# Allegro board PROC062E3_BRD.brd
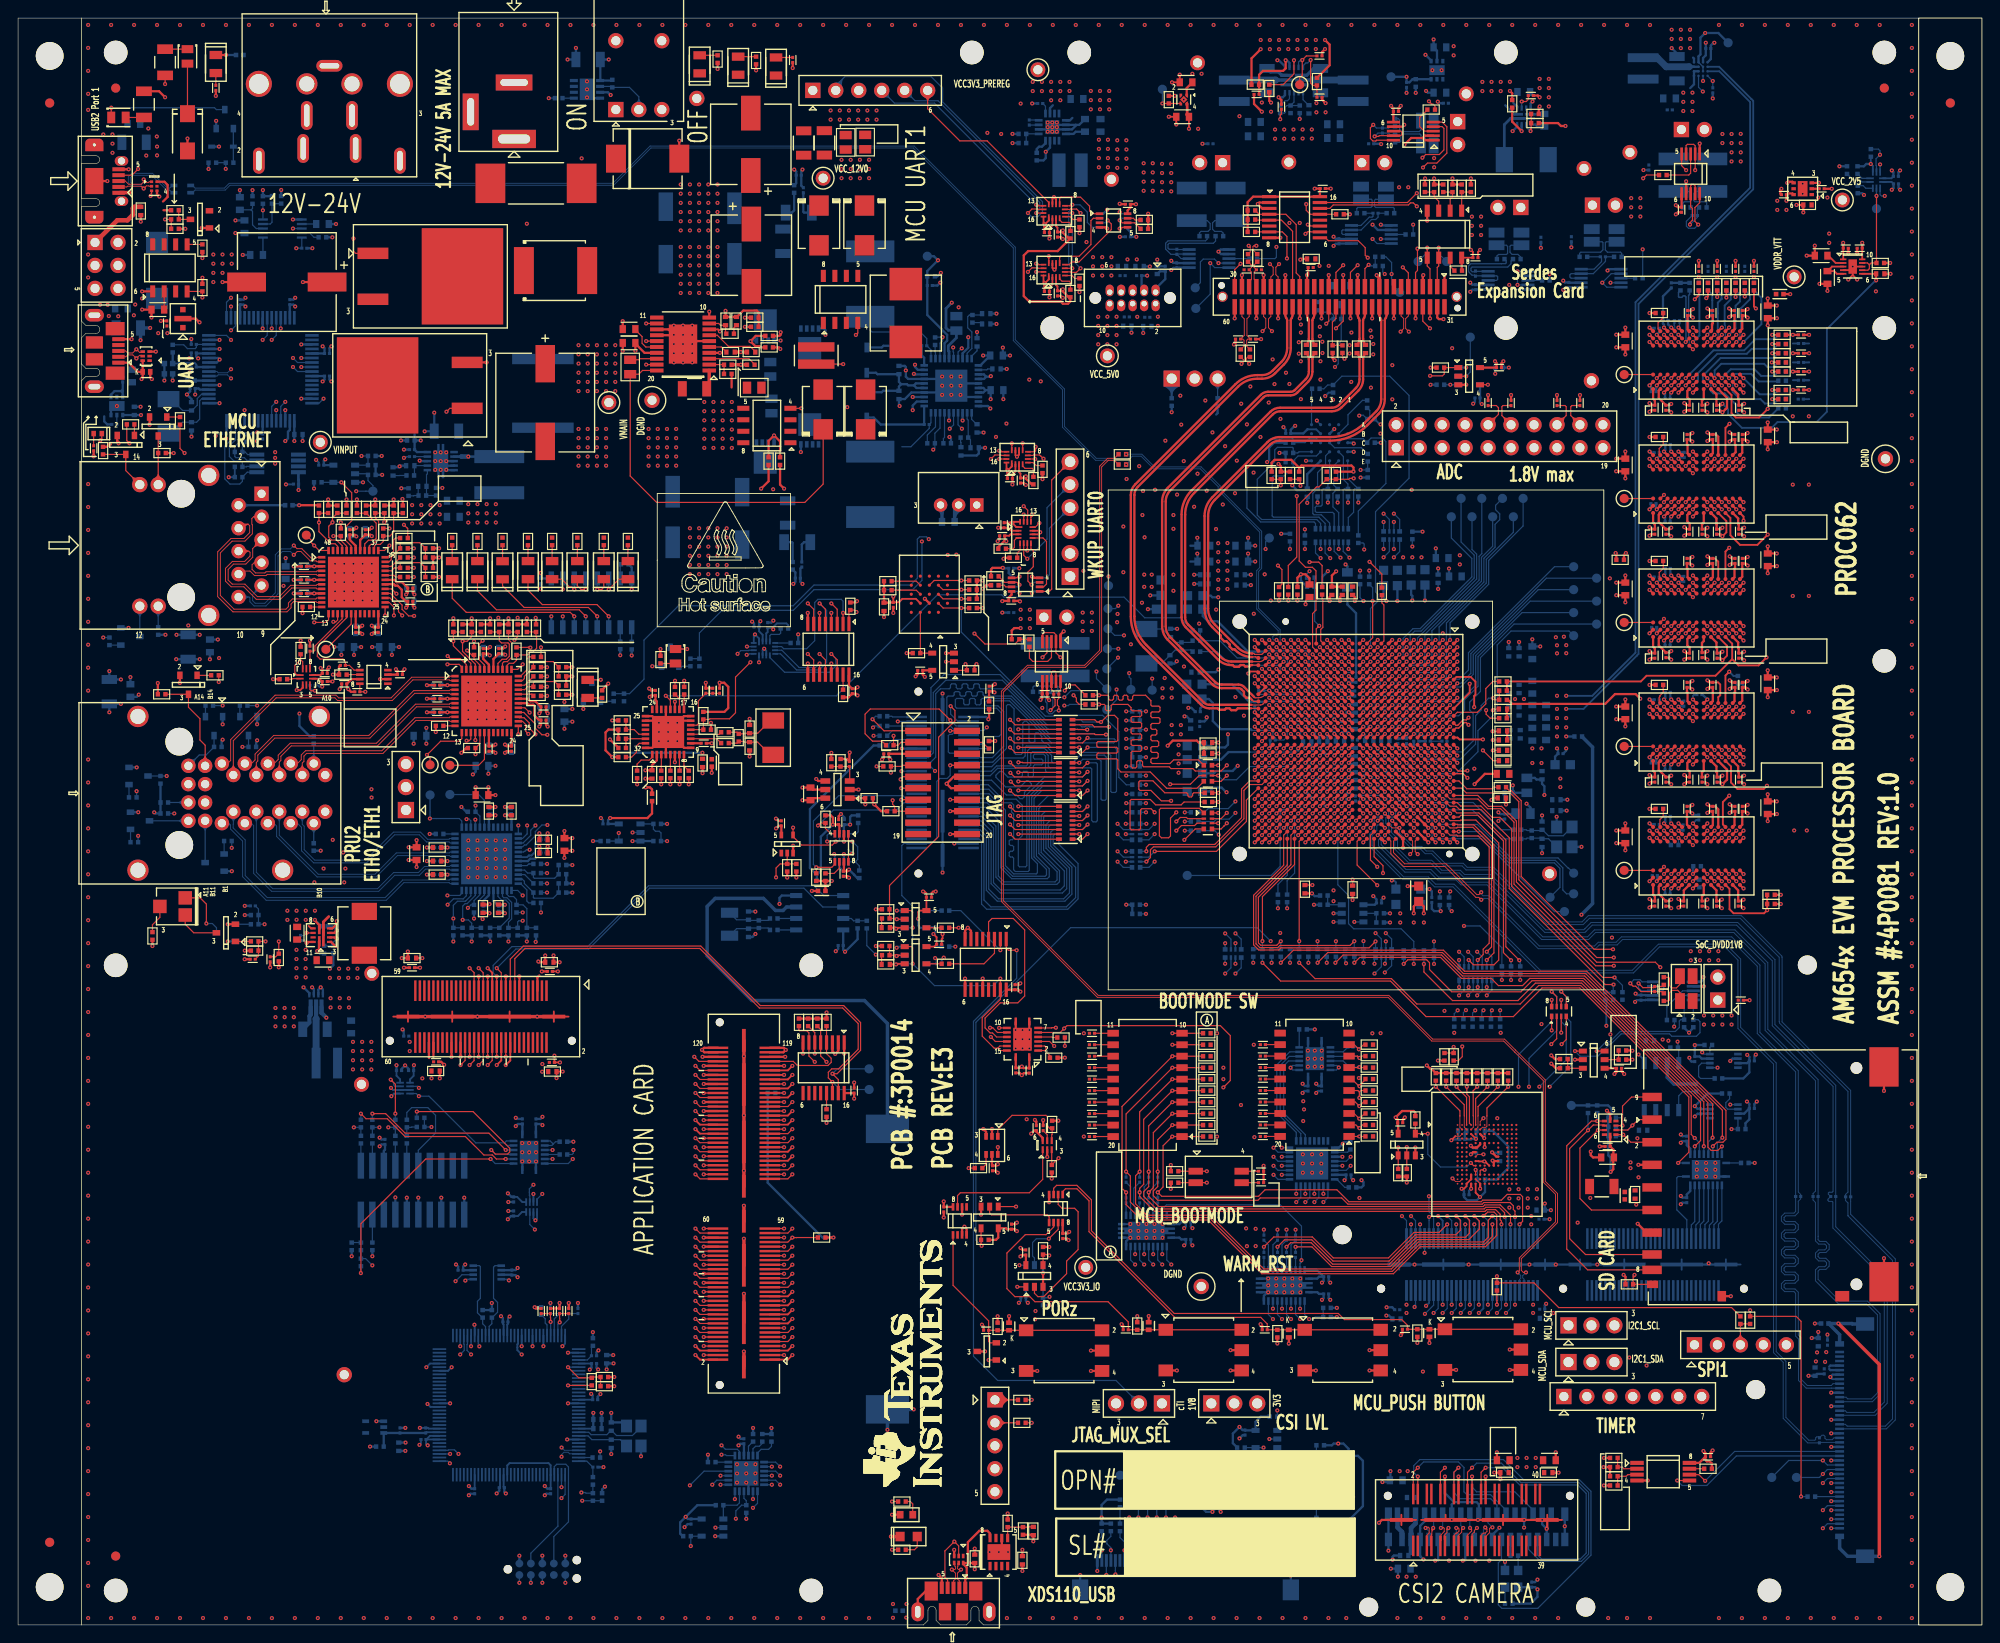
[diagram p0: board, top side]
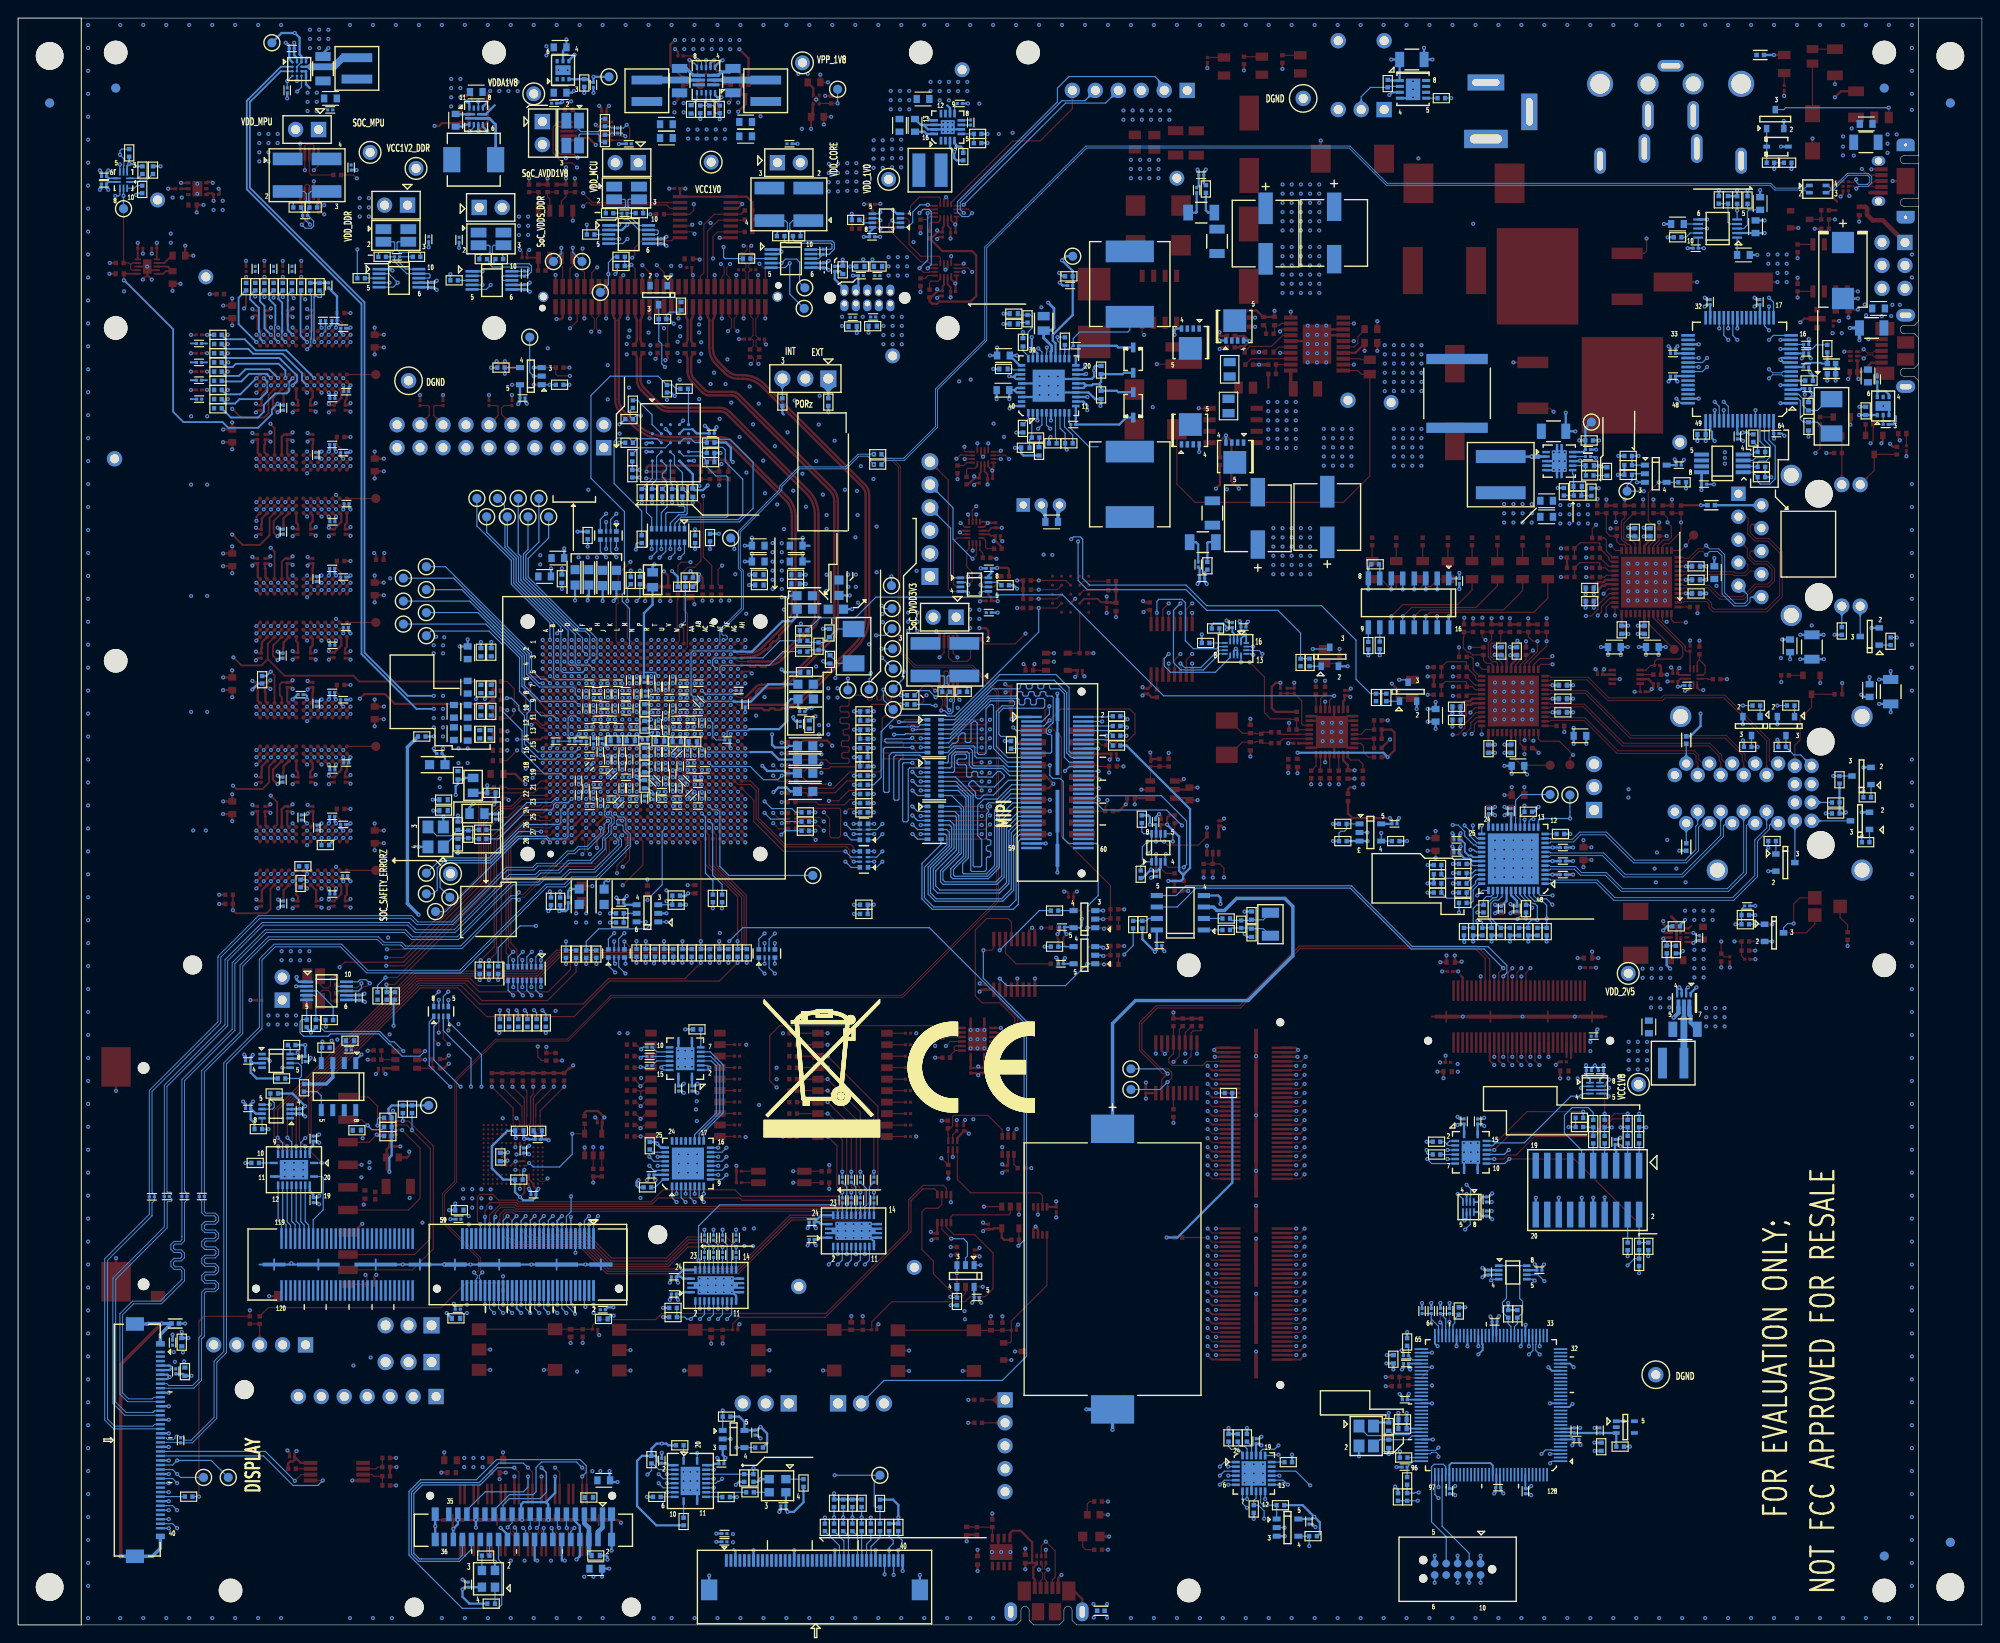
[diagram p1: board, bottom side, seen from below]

Outline 217.17 x 177.8 mm; copper layers: TOP, L02_GND1, L03_SIG1, L04_GND2, L05_SIG2, L06_PWR1, L07_PWR2, L08_PWR3, L09_GND3, L10_SIG3, L11_GND4, L12_SIG4, L13_GND5, BOTTOM. Coordinates in mm from the lower left corner of the outline.
Outline path: rectangle 210.19,0 217.17,177.8 ; 6.99,0 0,0 0,177.8 6.99,177.8 ; 6.99,0 6.99,137.65 7.48,138.15 8.58,138.15 arc(9.03,138.6) 8.58,139.05 7.48,139.05 6.99,139.55 6.99,142.39 7.48,142.89 8.58,142.89 arc(9.03,143.34) 8.58,143.79 7.48,143.79 6.99,144.29 6.99,156.97 8.6,156.97 arc(9.03,157.39) 8.6,157.82 6.99,157.82 6.99,161.72 8.6,161.72 arc(9.03,162.14) 8.6,162.57 6.99,162.57 6.99,177.8 ; 6.99,0 6.99,177.8 ; 6.99,0 100.12,0 100.12,0 100.62,0.5 100.62,1.6 arc(101.07,2.05) 101.52,1.6 101.52,0.5 102.02,0 104.87,0 104.87,0 105.37,0.5 105.37,1.6 arc(105.82,2.05) 106.27,1.6 106.27,0.5 106.77,0 210.19,0 210.19,177.8 6.99,177.8

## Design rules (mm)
net group CSI_REF_CLK_1V8: nets CSI_REF_CLK_1V8 N18001866
net group CSI_REF_CLK_3V3: nets CSI_REF_CLK_3V3 N18289892
net group DDR_DQ0: nets DDR_DQS0_N DDR_DQS0_P
net group DDR_DQS: nets DDR_DQS_N DDR_DQS_P
net group DDR_DQS1: nets DDR_DQS1_N DDR_DQS1_P
net group DDR_DQS2: nets DDR_DQS2_N DDR_DQS2_P
net group DDR_DQS3: nets DDR_DQS3_N DDR_DQS3_P
net group FT4232_USB_D: nets FT4232_USB_DM FT4232_USB_DP
net group MCU_ETH_D0: nets MCU_ETH_D0M MCU_ETH_D0P
net group MCU_ETH_D1: nets MCU_ETH_D1M MCU_ETH_D1P
net group MCU_ETH_D2: nets MCU_ETH_D2M MCU_ETH_D2P
net group MCU_ETH_D3: nets MCU_ETH_D3M MCU_ETH_D3P
net group MCU_RGMII1_CLKIN: nets MCU_RGMII1_CLKIN N16248965
net group MCU_SPI0_CLK/BOOTMODE6: nets MCU_SPI0_CLK MCU_SPI0_CLK/BOOTMODE6
net group MIPI_TRC_DAT00: nets PRG2_RGMII1_RD2 PRG2_RGMII1_RD2_R
net group MIPI_TRC_DAT01: nets PRG2_RGMII1_RD3 PRG2_RGMII1_RD3_R
net group MIPI_TRC_DAT02: nets PRG2_RGMII1_RX_CTL PRG2_RGMII1_RX_CTL_R
net group MIPI_TRC_DAT03: nets PRG2_RGMII1_RXC PRG2_RGMII1_RXC_R
net group MIPI_TRC_DAT05: nets MIPI_TRC_DAT05 PRG2_MDIO
net group MIPI_TRC_DAT11: nets PRG2_RGMII2_RD0 PRG2_RGMII2_RD0_R
net group MIPI_TRC_DAT12: nets PRG2_RGMII2_RD1 PRG2_RGMII2_RD1_R
net group MIPI_TRC_DAT13: nets PRG2_RGMII2_RD2 PRG2_RGMII2_RD2_R
net group MIPI_TRC_DAT14: nets PRG2_RGMII2_RD3 PRG2_RGMII2_RD3_R
net group MIPI_TRC_DAT15: nets PRG2_RGMII2_RX_CTL PRG2_RGMII2_RX_CTL_R
net group MIPI_TRC_DAT16: nets PRG2_RGMII2_RXC PRG2_RGMII2_RXC_R
net group MIPI_TRC_DAT18: nets MIPI_TRC_DAT18 PRG2_MDC
net group MMC0_CLK: nets MMC0_CLK SOC_MMC0_CLK
net group MMC0_DS: nets MMC0_DS SOC_MMC0_DS
net group OSPI_DQS: nets N15352717 OSPI_DQS
net group OSPI_LBCLKO_GPIO: nets OSPI_LBCLKO_GPIO PCIE_GPIO_RESET_IN
net group PCIE1_SGMII1_TXN1: nets PCIE1_SGMII1_TXN1 PCIE1_SGMII1_TXN1_C
net group PCIE1_SGMII1_TXP1: nets PCIE1_SGMII1_TXP1 PCIE1_SGMII1_TXP1_C
net group PRG0_RGMII1_ETH1_CLK: nets N16248943 PRG0_RGMII1_ETH1_CLK
net group PRG0_RGMII2_ETH2_CLK: nets N16248921 PRG0_RGMII2_ETH2_CLK
net group PRG1_RGMII1_ETH1_CLK: nets N16248899 PRG1_RGMII1_ETH1_CLK
net group PRG1_RGMII2_ETH2_CLK: nets N16248877 PRG1_RGMII2_ETH2_CLK
net group PRG2_ETH1_D0: nets PRG2_ETH1_D0M PRG2_ETH1_D0P
net group PRG2_ETH1_D1: nets PRG2_ETH1_D1M PRG2_ETH1_D1P
net group PRG2_ETH1_D2: nets PRG2_ETH1_D2M PRG2_ETH1_D2P
net group PRG2_ETH1_D3: nets PRG2_ETH1_D3M PRG2_ETH1_D3P
net group PRG2_ETH2_D0: nets PRG2_ETH2_D0M PRG2_ETH2_D0P
net group PRG2_ETH2_D1: nets PRG2_ETH2_D1M PRG2_ETH2_D1P
net group PRG2_ETH2_D2: nets PRG2_ETH2_D2M PRG2_ETH2_D2P
net group PRG2_ETH2_D3: nets PRG2_ETH2_D3M PRG2_ETH2_D3P
net group PRG2_RGMII1_ETH1_CLK: nets N16248855 PRG2_RGMII1_ETH1_CLK
net group PRG2_RGMII2_ETH2_CLK: nets N16248833 PRG2_RGMII2_ETH2_CLK
net group PWR: nets SOC_DDR_VREFCA SOC_DVDD1V8
net group REFCLK0N: nets REFCLK0N REFCLK0N_R
net group REFCLK0P: nets REFCLK0P REFCLK0P_R
net group REFCLK1N: nets REFCLK1N REFCLK1N_R
net group REFCLK1P: nets REFCLK1P REFCLK1P_R
net group SOC_MMC0_CMD: nets MMC0_CMD SOC_MMC0_CMD
net group SOC_MMC0_DAT0: nets MMC0_DAT0 SOC_MMC0_DAT0
net group SOC_MMC0_DAT1: nets MMC0_DAT1 SOC_MMC0_DAT1
net group SOC_MMC0_DAT2: nets MMC0_DAT2 SOC_MMC0_DAT2
net group SOC_MMC0_DAT3: nets MMC0_DAT3 SOC_MMC0_DAT3
net group SOC_MMC0_DAT4: nets MMC0_DAT4 SOC_MMC0_DAT4
net group SOC_MMC0_DAT5: nets MMC0_DAT5 SOC_MMC0_DAT5
net group SOC_MMC0_DAT6: nets MMC0_DAT6 SOC_MMC0_DAT6
net group SOC_MMC0_DAT7: nets MMC0_DAT7 SOC_MMC0_DAT7
net group SOC_SERDES_REFCLK0_: nets SOC_SERDES_REFCLK0_N SOC_SERDES_REFCLK0_P
net group SOC_SERDES_REFCLK1_: nets SOC_SERDES_REFCLK1_N SOC_SERDES_REFCLK1_P
net group SOC_SPI0_CLK: nets SOC_SPI0_CLK SOC_SPI0_CLK_R
net group SOC_SPI1_CLK: nets SOC_SPI1_CLK SOC_SPI1_CLK_R
net group SOC_TDO: nets N18125082 SOC_TDO
net group USB0_D: nets USB0_DM USB0_DP
net group USB1_AB_D: nets USB1_AB_DM USB1_AB_DP
net group USB1_CM_D: nets USB1_CM_DM USB1_CM_DP
net group USB1_D: nets USB1_DM USB1_DP
net group USB1_HDMI_GPMC_D: nets USB1_HDMI_GPMC_DM USB1_HDMI_GPMC_DP
net group WKUP_OSC0_XIN: nets N16248811 WKUP_OSC0_XIN
net group XDS_USB_D: nets XDS_USB_DM XDS_USB_DP
net group DDR_ADDRESS_BUS: nets DDR_A0 DDR_A1 DDR_A2 DDR_A3 DDR_A4 DDR_A5 DDR_A6 DDR_A7 DDR_A8 DDR_A9 DDR_A10 DDR_A11 DDR_A12 DDR_A13
net group DDR_DATA_BUS_PH: nets DDR_DM0 DDR_DM1 DDR_DM2 DDR_DM3 DDR_DM4 DDR_DQ0 DDR_DQ1 DDR_DQ2 DDR_DQ3 DDR_DQ4 DDR_DQ5 DDR_DQ6 DDR_DQ7 DDR_DQ8 DDR_DQ9 DDR_DQ10 DDR_DQ11 DDR_DQ12 DDR_DQ13 DDR_DQ14 DDR_DQ15 DDR_DQ16 DDR_DQ17 DDR_DQ18 DDR_DQ19 DDR_DQ20 DDR_DQ21 DDR_DQ22 DDR_DQ23 DDR_DQ24 DDR_DQ25 DDR_DQ26 DDR_DQ27 DDR_DQ28 DDR_DQ29 DDR_DQ30 DDR_DQ31 DDR_DQ36 DDR_DQ37 DDR_DQ38 DDR_DQ39 DDR_DQ40 DDR_DQ41 DDR_DQ42
net group MCU_RGMII1_RD0: nets MCU_RGMII1_RD0
net group MCU_RGMII1_RD1: nets MCU_RGMII1_RD1
net group MCU_RGMII1_RD2: nets MCU_RGMII1_RD2
net group MCU_RGMII1_RD3: nets MCU_RGMII1_RD3
net group MCU_RGMII1_RX_CTL: nets MCU_RGMII1_RX_CTL
net group MCU_RGMII1_RXC: nets MCU_RGMII1_RXC
net group MCU_RGMII1_TD0: nets MCU_RGMII1_TD0
net group MCU_RGMII1_TD1: nets MCU_RGMII1_TD1
net group MCU_RGMII1_TD2: nets MCU_RGMII1_TD2
net group MCU_RGMII1_TD3: nets MCU_RGMII1_TD3
net group MCU_RGMII1_TX_CTL: nets MCU_RGMII1_TX_CTL
net group MCU_RGMII1_TXC: nets MCU_RGMII1_TXC
net group MIPI_TRC_CLK: nets PRG2_PRU0_GP0 PRG2_RGMII1_RD0 PRG2_RGMII1_RD0_R
net group MIPI_TRC_CTL: nets PRG2_PRU0_GP1 PRG2_RGMII1_RD1 PRG2_RGMII1_RD1_R
net group MIPI_TRC_DAT04: nets PRG2_RGMII1_TX_CTL
net group MIPI_TRC_DAT06: nets PRG2_RGMII1_TD0
net group MIPI_TRC_DAT07: nets PRG2_RGMII1_TD1
net group MIPI_TRC_DAT08: nets PRG2_RGMII1_TD2
net group MIPI_TRC_DAT09: nets PRG2_RGMII1_TD3
net group MIPI_TRC_DAT10: nets PRG2_RGMII1_TXC
net group MIPI_TRC_DAT17: nets PRG2_RGMII2_TX_CTL
net group MIPI_TRC_DAT19: nets PRG2_RGMII2_TD0
net group MIPI_TRC_DAT20: nets PRG2_RGMII2_TD1
net group MIPI_TRC_DAT21: nets PRG2_RGMII2_TD2
net group MIPI_TRC_DAT22: nets PRG2_RGMII2_TD3
net group MIPI_TRC_DAT23: nets PRG2_RGMII2_TXC
net group OSPI_CLK: nets N20584902 OSPI_CLK SOC_OSPI_CLK
net group SOC_TCK: nets N16937764 N16938293 SOC_TCK
net group USB0_PCIE0_SGMII0_TXN0: nets USB0_PCIE0_SGMII0_TXN0_C

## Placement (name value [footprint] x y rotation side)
ACC*  -  [unnamed#3]  147.96 98.17 270 top
B1  796136-1  [BATTH2_796136_1080X750_SMD_6-9]  96.14 39.37 270 bottom
C1  1uF  [CAP0603_1]  128.78 166.88 180 top
C2  0.01uF  [CAP0201_0-5]  136.96 169.35 180 top
C3  0.01uF  [CAP0201_0-5]  167.28 169.23 0 top
C4  0.1uF  [CAP0201_0-5]  139.7 167.98 270 top
C5  1uF  [CAP0603_1]  129.16 170.69 180 top
C6  0.1uF  [CAP0201_0-5]  152.37 167.47 0 top
C7  0.47uF  [CAP0805_1]  93.68 164.08 90 top
C8  0.47uF  [CAP0805_1]  91.52 164.05 90 top
C9  47uF  [CAP1206_2]  89.17 163.99 90 top
C10  47uF  [CAP1206_2]  86.88 163.97 90 top
C11  1000pF  [CAP1206]  12.83 164.06 180 bottom
C12  150uF_25V  [CAPAE_CASE8383_11]  81.03 163.83 90 top
C13  0.1uF  [CAP0201_0-5]  144.27 158.94 0 top
C14  0.01uF  [CAP0201_0-5]  199.44 158.91 0 top
C15  0.1uF  [CAP0201_0-5]  195.28 158.26 180 top
C16  0.1uF  [CAP0201_0-5]  122.73 157.2 180 top
C17  2.2uF  [CAP0402_0-75]  197.88 157.12 180 top
C18  0.1uF  [CAP0201_0-5]  183.96 156.59 270 top
C19  4.7uF  [CAP0402_0-75]  13.57 156.45 270 top
C20  0.1uF  [CAP0201_0-5]  113.78 154.06 180 top
C21  0.1uF  [CAP0201_0-5]  114.94 153.85 270 top
C22  0.1uF  [CAP0201_0-5]  202.11 152.34 0 top
C23  0.1uF  [CAP0201_0-5]  203.65 152.34 180 top
C24  150uF_25V  [CAPAE_CASE8383_11]  81.09 151.56 270 top
C25  10uF  [CAP0603_1]  199.39 151.51 180 top
C26  1uF  [CAP0402_0-75]  143 151.15 180 top
C29  0.1uF  [CAP0201_0-5]  142.94 150.2 180 top
C30  0.1uF  [CAP0201_0-5]  185.86 150.05 90 top
C31  0.1uF  [CAP0201_0-5]  190.94 150.05 90 bottom
C32  0.1uF  [CAP0201_0-5]  187.9 150.05 90 top
C33  0.1uF  [CAP0201_0-5]  188.91 150.05 90 bottom
C34  0.1uF  [CAP0201_0-5]  189.93 150.05 90 top
C35  0.1uF  [CAP0201_0-5]  186.88 150.05 90 bottom
C36  0.1uF  [CAP0201_0-5]  191.96 150.05 90 top
C37  0.22uF  [CAP0402_0-75]  205.93 149.5 0 top
C38  10uF  [CAP0603_1]  200.09 149.1 90 top
C39  22uF_100V  [CAPAE_GCASE]  29.72 148.59 180 top
C40  0.1uF  [CAP0201_0-5]  113.78 147.55 180 top
C41  0.1uF  [CAP0201_0-5]  114.94 147.34 270 top
C42  10uF  [CAP0603_1]  15.45 145.54 180 top
C43  22uF_6.3V  [CAP0603]  193.48 145.29 270 top
C44  0.01uF  [CAP0201_0-5]  184.62 145.16 90 top
C45  0.01uF  [CAP0201_0-5]  187.41 145.16 90 top
C46  0.01uF  [CAP0201_0-5]  189.81 145.16 90 top
C47  0.01uF  [CAP0201_0-5]  190.66 145.16 90 top
C48  100pF  [CAP0402]  78.23 144.27 90 top
C49  820pF  [CAP0402_0-75]  79.44 144.27 90 top
C50  0.1uF  [CAP0201_0-5]  16.45 144.01 90 top
C51  1uF  [CAP0603_1]  67.56 143.38 180 top
C52  0.1uF  [CAP0201_0-5]  197.17 142.75 0 top
C53  22uF_6.3V  [CAP0603]  177.74 142.07 270 top
C56  1uF  [CAP0603_1]  67.56 141.86 180 top
C57  0.1uF  [CAP0201_0-5]  197.17 141.8 0 bottom
C58  0.01uF  [CAP0402_0-75]  142.47 141.18 90 top
C59  0.01uF  [CAP0402_0-75]  143.41 141.18 90 top
C60  0.01uF  [CAP0402_0-75]  148.07 141.18 90 top
C61  0.01uF  [CAP0402_0-75]  149.01 141.18 90 top
C62  220pF  [CAP0402]  78.79 140.84 0 top
C63  0.047uF  [CAP0402_0-75]  81.07 140.84 180 top
C64  0.1uF  [CAP0201_0-5]  197.17 140.71 0 top
C65  0.1uF  [CAP0201_0-5]  197.17 139.7 0 bottom
C66  0.47uF  [CAP0805_1]  67.69 139.19 270 top
C67  0.1uF  [CAP0201_0-5]  197.17 138.68 0 top
C68  2.2uF  [CAP0805_1]  81.41 136.91 0 top
C69  10uF  [CAP1206_2]  74.8 136.78 180 top
C70  0.1uF  [CAP0201_0-5]  197.17 136.65 0 top
C71  0.1uF  [CAP0201_0-5]  197.14 135.64 0 bottom
C72  100uF_63V  [CAPAE_CASE103103_11]  58.29 135.25 270 top
C73  0.1uF  [CAP0201_0-5]  162.56 135.2 90 top
C74  0.1uF  [CAP0201_0-5]  165.1 135.2 90 top
C75  0.1uF  [CAP0201_0-5]  170.18 135.2 90 top
C76  0.1uF  [CAP0201_0-5]  172.72 135.2 90 top
C77  1000pF  [CAP1206]  12.19 143.51 180 bottom
C78  0.01uF  [CAP0201_0-5]  181 134.68 270 top
C79  0.01uF  [CAP0201_0-5]  182.21 134.68 270 top
C80  0.01uF  [CAP0201_0-5]  184.85 134.68 270 top
C81  0.01uF  [CAP0201_0-5]  186.21 134.68 270 top
C82  0.01uF  [CAP0201_0-5]  187.81 134.68 270 top
C83  0.01uF  [CAP0201_0-5]  190.28 134.68 270 top
C85  22uF_6.3V  [CAP0603]  193.48 131.57 90 top
C86  0.01uF  [CAP0201_0-5]  184.55 131.44 90 top
C87  0.01uF  [CAP0201_0-5]  187.41 131.44 90 top
C88  0.01uF  [CAP0201_0-5]  189.86 131.44 90 top
C89  0.01uF  [CAP0201_0-5]  190.66 131.44 90 top
C90  22uF_6.3V  [CAP0603]  177.74 128.35 270 top
C91  0.1uF  [CAP0201_0-5]  109.68 126.84 180 top
C92  0.1uF  [CAP0201_0-5]  110.85 126.63 270 top
C94  0.1uF  [CAP0201_0-5]  109.04 121.68 90 top
C95  0.01uF  [CAP0201_0-5]  181 120.97 270 top
C96  0.01uF  [CAP0201_0-5]  182.21 120.97 270 top
C97  0.01uF  [CAP0201_0-5]  184.85 120.97 270 top
C98  0.01uF  [CAP0201_0-5]  186.21 120.97 270 top
C99  0.01uF  [CAP0201_0-5]  187.83 120.97 270 top
C100  0.01uF  [CAP0201_0-5]  190.27 120.97 270 top
C101  0.1uF  [CAP0201_0-5]  36.68 120.9 90 top
C102  0.1uF  [CAP0201_0-5]  38.39 120.9 90 top
C103  0.1uF  [CAP0201_0-5]  108.83 120.52 180 top
C104  22uF_6.3V  [CAP0603]  193.48 117.86 90 top
C105  0.01uF  [CAP0201_0-5]  184.55 117.73 90 top
C106  0.01uF  [CAP0201_0-5]  187.41 117.73 90 top
C107  0.01uF  [CAP0201_0-5]  189.87 117.73 90 top
C108  0.01uF  [CAP0201_0-5]  190.66 117.73 90 top
C109  0.1uF  [CAP0201_0-5]  31.61 117.14 180 top
C110  0.1uF  [CAP0201_0-5]  31.63 115.64 180 top
C111  0.1uF  [CAP0201_0-5]  43.37 114.74 0 top
C112  22uF_6.3V  [CAP0603]  177.74 114.63 270 top
C113  2.2uF  [CAP0603]  142.81 114.43 270 top
C114  1uF  [CAP0402_0-75]  145.29 114.43 90 top
C115  2.2uF  [CAP0402_0-75]  146.43 114.43 90 top
C116  1uF  [CAP0402_0-75]  147.57 114.43 90 top
C117  0.1uF  [CAP0201_0-5]  31.61 114.14 180 top
C119  0.1uF  [CAP0201_0-5]  109.83 113.31 0 top
C120  0.1uF  [CAP0201_0-5]  43.37 113.28 0 top
C121  0.1uF  [CAP0201_0-5]  96.79 112.87 270 top
C122  4.7uF  [CAP0402_0-75]  95.76 112.65 270 top
C123  0.1uF  [CAP0201_0-5]  37.33 110.11 270 top
C124  0.1uF  [CAP0201_0-5]  39.83 110.11 270 top
C125  0.1uF  [CAP0201_0-5]  51.44 107.75 90 top
C126  0.1uF  [CAP0201_0-5]  53.15 107.75 90 top
C127  0.01uF  [CAP0201_0-5]  182.21 107.31 270 top
C128  0.01uF  [CAP0201_0-5]  186.21 107.31 270 top
C129  0.01uF  [CAP0201_0-5]  181 107.25 270 top
C130  0.01uF  [CAP0201_0-5]  184.85 107.25 270 top
C131  0.01uF  [CAP0201_0-5]  187.88 107.25 270 top
C132  0.01uF  [CAP0201_0-5]  190.27 107.25 270 top
C133  0.1uF  [CAP0201_0-5]  99.76 105.63 180 top
C134  0.1uF  [CAP0201_0-5]  33.91 105.28 0 top
C135  0.1uF  [CAP0201_0-5]  42.23 105.16 0 top
C136  0.1uF  [CAP0201_0-5]  33.91 104.39 0 top
C137  22uF_6.3V  [CAP0603]  193.48 104.14 90 top
C138  0.1uF  [CAP0201_0-5]  36.07 104.14 180 top
C139  0.01uF  [CAP0201_0-5]  184.55 104.01 90 top
C140  0.01uF  [CAP0201_0-5]  187.41 104.01 90 top
C141  0.01uF  [CAP0201_0-5]  189.87 104.01 90 top
C142  0.01uF  [CAP0201_0-5]  190.66 104.01 90 top
C143  0.1uF  [CAP0201_0-5]  46.34 103.98 180 top
C144  0.1uF  [CAP0201_0-5]  107.38 103.59 90 top
C145  0.1uF  [CAP0201_0-5]  76.83 103.37 90 top
C146  0.1uF  [CAP0201_0-5]  92.23 103.32 270 top
C147  0.1uF  [CAP0201_0-5]  70.48 103.12 90 top
C148  0.1uF  [CAP0201_0-5]  113.53 103.03 0 top
C149  0.1uF  [CAP0201_0-5]  46.36 102.48 180 top
C150  0.1uF  [CAP0201_0-5]  58.1 101.59 0 top
C151  1uF  [CAP0402_0-75]  164.21 101.35 0 top
C153  0.1uF  [CAP0201_0-5]  46.34 100.99 180 top
C154  22uF_6.3V  [CAP0603]  177.74 100.92 270 top
C155  0.1uF  [CAP0201_0-5]  58.1 100.13 0 top
C156  18pF  [CAP0402_0-75]  80.9 99.13 270 top
C157  1uF  [CAP0402_0-75]  164.21 98.93 0 top
C158  1uF  [CAP0402_0-75]  164.21 97.92 0 top
C159  1uF  [CAP0402_0-75]  131.6 97.64 180 top
C160  0.1uF  [CAP0201_0-5]  75.82 97.56 0 top
C161  18pF  [CAP0402_0-75]  80.9 97.22 90 top
C162  0.1uF  [CAP0201_0-5]  52.07 96.96 270 top
C163  0.1uF  [CAP0201_0-5]  54.57 96.96 270 top
C164  1uF  [CAP0402_0-75]  164.21 96.77 0 top
C165  1uF  [CAP0402_0-75]  131.6 96.43 180 top
C166  0.1uF  [CAP0201_0-5]  96.01 96.39 180 top
C167  1uF  [CAP0402_0-75]  164.21 95.63 0 top
C168  0.01uF  [CAP0201_0-5]  91.92 95.26 90 top
C169  1uF  [CAP0402_0-75]  75.69 95.38 90 top
C170  2.2uF  [CAP0603]  164.21 94.17 180 top
C171  1uF  [CAP0402_0-75]  70.1 94.11 90 top
C172  0.01uF  [CAP0201_0-5]  181 93.54 270 top
C173  0.01uF  [CAP0201_0-5]  182.21 93.54 270 top
C174  0.01uF  [CAP0201_0-5]  184.85 93.54 270 top
C175  0.01uF  [CAP0201_0-5]  186.21 93.54 270 top
C176  0.01uF  [CAP0201_0-5]  187.88 93.54 270 top
C177  0.01uF  [CAP0201_0-5]  190.27 93.54 270 top
C178  10uF  [CAP0603_1]  51.3 91.82 180 top
C179  0.1uF  [CAP0603_1]  87.63 91.96 270 top
C180  2.2uF  [CAP0402_0-75]  164.08 91.5 0 top
C181  22uF_6.3V  [CAP0603]  193.48 90.42 90 top
C182  0.01uF  [CAP0201_0-5]  184.55 90.3 90 top
C183  0.01uF  [CAP0201_0-5]  187.41 90.3 90 top
C184  0.01uF  [CAP0201_0-5]  189.87 90.3 90 top
C185  0.01uF  [CAP0201_0-5]  190.66 90.3 90 top
C186  1uF  [CAP0402_0-75]  52.07 90.05 90 top
C187  1uF  [CAP0402_0-75]  54.57 90.05 90 top
C188  0.1uF  [CAP0201_0-5]  90.74 88.84 90 top
C189  0.1uF  [CAP0201_0-5]  84.4 88.7 90 top
C190  22uF_6.3V  [CAP0603]  177.74 87.2 270 top
C192  1uF  [CAP0402_0-75]  58.1 86.88 0 top
C193  10uF  [CAP0603_1]  60.41 86.36 90 top
C194  1uF  [CAP0402_0-75]  46.34 86.02 180 top
C195  1uF  [CAP0402_0-75]  58.1 85.41 0 top
C196  10uF  [CAP0603_1]  44.07 85.34 270 top
C197  1uF  [CAP0402_0-75]  46.34 84.52 180 top
C198  0.1uF  [CAP0201_0-5]  91.25 83.12 270 top
C199  1uF  [CAP0402_0-75]  46.34 83.02 180 top
C200  2.2uF  [CAP0402_0-75]  142.3 81.41 270 top
C201  1uF  [CAP0402_0-75]  147.57 81.34 270 top
C202  0.01uF  [CAP0201_0-5]  181 79.82 270 top
C203  0.01uF  [CAP0201_0-5]  182.21 79.82 270 top
C204  0.01uF  [CAP0201_0-5]  184.2 79.82 270 top
C205  0.01uF  [CAP0201_0-5]  186.21 79.82 270 top
C206  0.01uF  [CAP0201_0-5]  187.81 79.82 270 top
C207  0.01uF  [CAP0201_0-5]  190.21 79.82 270 top
C208  1uF  [CAP0402_0-75]  51.41 79.26 270 top
C209  1uF  [CAP0402_0-75]  53.11 79.26 270 top
C210  8.2pF  [CAP0402_0-75]  95.95 77.15 0 top
C211  10uF  [CAP0603_1]  30.86 76.54 270 top
C212  22uF_6.3V  [CAP0603]  33.72 73.56 180 top
C213  1uF  [CAP0402_0-75]  43.56 73.79 180 top
C214  8.2pF  [CAP0402_0-75]  95.95 73.09 0 top
C215  0.1uF  [CAP0201_0-5]  42.93 65.15 180 bottom
C216  0.1uF  [CAP0201_0-5]  43.56 72.72 180 top
C217  0.1uF  [CAP0201_0-5]  110.24 70.57 90 top
C218  0.1uF  [CAP0201_0-5]  180.98 70.36 90 top
C219  0.1uF  [CAP0201_0-5]  190.51 69.13 0 top
C220  0.1uF  [CAP0201_0-5]  186.06 56.84 270 bottom
C221  0.1uF  [CAP0201_0-5]  191.73 57.15 0 bottom
C222  0.1uF  [CAP0201_0-5]  58.8 72.31 0 top
C223  0.1uF  [CAP0201_0-5]  59.03 62.24 0 top
C224  0.01uF  [CAP0201_0-5]  177.04 61.6 180 top
C225  0.1uF  [CAP0201_0-5]  110.32 61.36 270 top
C226  0.1uF  [CAP0201_0-5]  111.82 61.34 270 top
C227  1uF  [CAP0402_0-75]  58.75 73.33 0 top
C228  1uF  [CAP0402_0-75]  59.09 61.23 0 top
C229  0.1uF  [CAP0201_0-5]  92.46 59.13 90 top
C230  0.1uF  [CAP0201_0-5]  152.84 55.56 0 top
C231  0.1uF  [CAP0201_0-5]  112.6 54.98 90 top
C232  0.1uF  [CAP0201_0-5]  113.36 54.98 90 top
C233  0.1uF  [CAP0201_0-5]  175.78 52.95 180 top
C234  0.1uF  [CAP0201_0-5]  107.75 50.54 270 top
C235  2.2uF  [CAP0402_0-75]  178.82 47.62 270 top
C236  0.1uF  [CAP0201_0-5]  102.36 45.97 270 top
C237  0.1uF  [CAP0201_0-5]  109.86 44.07 90 top
C238  0.1uF  [CAP0201_0-5]  115.52 43.04 270 top
C239  0.1uF  [CAP0201_0-5]  111.45 41.21 90 top
C240  0.1uF  [CAP0201_0-5]  153.37 32.72 180 top
C241  0.1uF  [CAP0201_0-5]  137.86 32.65 180 top
C242  0.1uF  [CAP0201_0-5]  122.49 32.65 180 top
C243  0.1uF  [CAP0201_0-5]  107.05 32.6 180 top
C244  0.01uF  [CAP0201_0-5]  186.88 18.61 0 top
C245  10uF  [CAP0603_1]  164.24 18.22 0 top
C246  10uF  [CAP0603_1]  169.34 18.22 180 top
C247  1uF  [CAP0402_0-75]  164.38 16.85 0 top
C248  1uF  [CAP0402_0-75]  169.22 16.85 180 top
C249  15pF  [CAP0402_0-75]  112.27 10.39 90 top
C250  2.2uF  [CAP0402_0-75]  105.79 7.31 90 top
C251  1uF  [CAP0402_0-75]  111.06 7.15 90 top
C252  0.1uF  [CAP0201_0-5]  186.91 174.43 180 bottom
C253  1uF  [CAP0603_1]  157.23 174.56 180 bottom
C254  10uF  [CAP1206_2]  63.04 173.22 180 bottom
C255  10uF  [CAP1206_2]  183.45 172.2 270 bottom
C256  22uF  [CAP1206_2]  144.02 170.88 270 bottom
C257  22uF  [CAP1206_2]  138.11 170.88 270 bottom
C258  0.01uF  [CAP0201_0-5]  153.54 170.41 270 bottom
C259  1uF  [CAP0603_1]  157.23 169.55 180 bottom
C260  10uF  [CAP0603_1]  166.5 169.62 0 bottom
C261  22uF_6.3V  [CAP0603]  182.63 168.91 0 bottom
C262  22uF_6.3V  [CAP0603]  117.1 168.85 0 bottom
C263  0.1uF  [CAP0201_0-5]  157.89 168.38 180 bottom
C264  0.01uF  [CAP0201_0-5]  113.03 168.35 180 bottom
C265  0.01uF  [CAP0402_0-75]  142.75 167.7 270 bottom
C266  0.1uF  [CAP0201_0-5]  182.65 167.64 0 bottom
C267  22uF_6.3V  [CAP0603]  168.78 166.5 90 bottom
C268  47uF  [CAP0603_1]  136.72 166.31 0 bottom
C269  0.01uF  [CAP0201_0-5]  111.82 166.24 270 bottom
C270  47uF  [CAP0603_1]  145.48 166.05 180 bottom
C271  22uF_6.3V  [CAP0603]  119.7 165.93 90 bottom
C272  22uF_6.3V  [CAP0603]  117.98 165.93 90 bottom
C273  0.1uF  [CAP0201_0-5]  150.88 165.35 270 bottom
C274  47uF  [CAP0603_1]  136.72 164.72 0 bottom
C275  47uF  [CAP0603_1]  145.48 164.53 180 bottom
C276  0.1uF  [CAP0201_0-5]  149.63 163.89 0 bottom
C277  0.1uF  [CAP0201_0-5]  131.86 163.89 180 bottom
C278  0.1uF  [CAP0201_0-5]  180.34 161.26 270 bottom
C279  0.1uF  [CAP0201_0-5]  185.42 155.96 0 bottom
C280  0.1uF  [CAP0201_0-5]  150.11 156.21 0 bottom
C281  0.1uF  [CAP0603_1]  33.67 155.01 0 bottom
C282  0.1uF  [CAP0603_1]  25.03 154.71 90 bottom
C283  470uF_10V  [CAPAE_D8CASE_8]  71.63 154.03 270 bottom
C284  270uF_10V  [CAP_87510524_270X270_SMD_7-7]  79.22 153.95 270 bottom
C285  0.1uF  [CAP0201_0-5]  122.73 153.59 180 bottom
C286  0.1uF  [CAP0201_0-5]  128.14 151.94 270 bottom
C287  0.1uF  [CAP0201_0-5]  171.77 153.33 270 bottom
C288  0.1uF  [CAP0201_0-5]  168.4 153.26 270 bottom
C289  0.1uF  [CAP0201_0-5]  146.07 153.1 90 bottom
C290  47uF  [CAP1206_2]  84.58 153.1 270 bottom
C291  0.01uF  [CAP0201_0-5]  31.65 152.34 0 bottom
C292  0.1uF  [CAP0201_0-5]  175.26 151.38 0 bottom
C293  0.1uF  [CAP0201_0-5]  161.16 149.52 270 bottom
C294  0.1uF  [CAP0201_0-5]  128.12 150.44 90 bottom
C295  1uF  [CAP0402_0-75]  124.02 150.31 180 bottom
C296  1uF  [CAP0402_0-75]  122.07 150.31 0 bottom
C297  0.1uF  [CAP0201_0-5]  126.86 150.06 90 bottom
C298  1uF  [CAP0402_0-75]  125.98 149.94 90 bottom
C299  150uF_10V  [CAPT7343D_3-25]  15.37 149.87 270 bottom
C300  0.1uF  [CAP0201_0-5]  123.97 149.3 180 bottom
C301  0.1uF  [CAP0201_0-5]  122.15 149.3 0 bottom
C302  0.1uF  [CAP0201_0-5]  171.5 148.27 90 bottom
C303  0.1uF  [CAP0201_0-5]  182.82 148.22 90 bottom
C304  0.1uF  [CAP0201_0-5]  161.18 148.02 90 bottom
C305  0.1uF  [CAP0201_0-5]  30.05 146.37 270 bottom
C306  0.1uF  [CAP0201_0-5]  24.55 146.37 270 bottom
C307  0.01uF  [CAP0402_0-75]  107.06 143.95 0 bottom
C308  100pF  [CAP0402]  107.06 145.1 0 bottom
C309  0.1uF  [CAP0201_0-5]  122.61 144.73 0 bottom
C310  0.1uF  [CAP0201_0-5]  124.87 144.69 180 bottom
C311  0.01uF  [CAP0201_0-5]  183.45 144.34 0 bottom
C312  0.01uF  [CAP0201_0-5]  182.18 144.34 0 bottom
C313  1uF  [CAP0402_0-75]  122.67 143.71 0 bottom
C314  1uF  [CAP0402_0-75]  124.88 143.68 180 bottom
C315  0.01uF  [CAP0201_0-5]  181.22 143.49 180 bottom
C316  0.01uF  [CAP0201_0-5]  100.83 148.21 0 bottom
C317  0.056uF  [CAP0402_0-75]  106.05 141.92 90 bottom
C318  0.47uF  [CAP0603_1]  108.25 136.63 0 bottom
C319  0.1uF  [CAP0201_0-5]  19.43 141.69 0 bottom
C320  0.1uF  [CAP0201_0-5]  100.2 141.54 0 bottom
C321  0.1uF  [CAP0201_0-5]  19.43 140.75 0 bottom
C322  0.1uF  [CAP0201_0-5]  34.16 140.69 180 bottom
C323  0.1uF  [CAP0603_1]  108.2 140.46 0 bottom
C324  0.1uF  [CAP0201_0-5]  19.43 139.19 0 bottom
C325  1uF  [CAP0402_0-75]  108.2 138.97 180 bottom
C326  0.1uF  [CAP0201_0-5]  34.16 138.19 180 bottom
C327  10uF  [CAP0603_1]  12.6 138.2 270 bottom
C328  0.1uF  [CAP0201_0-5]  197.17 137.73 0 bottom
C329  0.1uF  [CAP0201_0-5]  11.57 137.82 270 bottom
C330  4.7uF  [CAP0402_0-75]  97.41 138.85 90 bottom
C331  0.1uF  [CAP0201_0-5]  19.3 136.82 0 bottom
C332  0.01uF  [CAP0201_0-5]  180.88 136.46 180 bottom
C333  22uF  [CAP7563_4]  58.04 136.27 270 bottom
C334  0.1uF  [CAP0201_0-5]  161.38 135.76 180 bottom
C335  0.01uF  [CAP0201_0-5]  182.41 135.7 0 bottom
C336  1uF  [CAP0603_1]  102.87 122.05 180 bottom
C337  18pF  [CAP0402_0-75]  19.18 134.84 90 bottom
C338  0.01uF  [CAP0201_0-5]  187.81 134.68 270 bottom
C339  2.2uF  [CAP0402_0-75]  12.85 134.33 90 bottom
C340  0.47uF  [CAP0805_1-5]  103.76 144.02 90 bottom
C341  10uF  [CAP1206_2]  47.37 132.08 180 bottom
C342  0.01uF  [CAP0201_0-5]  10.64 132.84 180 bottom
C343  0.1uF  [CAP0201_0-5]  100.48 132.83 180 bottom
C344  18pF  [CAP0402_0-75]  19.18 132.62 270 bottom
C345  0.056uF  [CAP0402_0-75]  106.05 132.4 270 bottom
C346  0.1uF  [CAP0201_0-5]  140.46 131.84 180 bottom
C347  3.3uF  [CAP0402]  31.01 131.72 180 bottom
C348  0.1uF  [CAP0201_0-5]  27.05 131.51 90 bottom
C349  0.1uF  [CAP0201_0-5]  22.73 131.83 0 bottom
C350  100pF  [CAP0402]  105.78 130.25 0 bottom
C351  0.01uF  [CAP0201_0-5]  182.44 130.62 0 bottom
C352  0.01uF  [CAP0402_0-75]  104.27 129.86 270 bottom
C353  0.01uF  [CAP0201_0-5]  43.56 130.05 180 bottom
C354  0.01uF  [CAP0201_0-5]  181.22 129.71 180 bottom
C355  0.01uF  [CAP0201_0-5]  184.25 129.47 90 bottom
C356  0.1uF  [CAP0201_0-5]  43.56 129.28 180 bottom
C357  150pF  [CAP0402_0-75]  43.37 128.27 180 bottom
C358  0.1uF  [CAP0201_0-5]  33.53 128.33 180 bottom
C359  0.015uF  [CAP0402]  41.47 127.64 270 bottom
C360  0.1uF  [CAP0201_0-5]  30.73 126.24 0 bottom
C361  200pF  [CAP0402_0-75]  44.7 125.98 0 bottom
C362  4.7uF  [CAP0402_0-75]  142.56 125.29 270 bottom
C363  22uF_6.3V  [CAP0603]  48.13 124.39 180 bottom
C364  0.01uF  [CAP0201_0-5]  180.85 124.08 180 bottom
C365  47uF  [CAP1206_2]  85.1 123.03 90 bottom
C366  22uF_6.3V  [CAP0603]  48.13 122.61 180 bottom
C367  470uF_10V  [CAPAE_D8CASE_8]  80.07 122.44 90 bottom
C368  270uF_10V  [CAP_87510524_270X270_SMD_7-7]  72.39 122.59 90 bottom
C369  0.01uF  [CAP0201_0-5]  182.41 122.06 0 bottom
C370  0.01uF  [CAP0201_0-5]  187.83 120.97 270 bottom
C371  1uF  [CAP0402_0-75]  38.39 120.9 90 bottom
C372  1uF  [CAP0402_0-75]  36.68 120.9 90 bottom
C373  10uF  [CAP0603_1]  135.32 119.42 0 bottom
C374  10uF  [CAP0603_1]  131.13 119.42 180 bottom
C375  10uF  [CAP0603_1]  157.48 118.05 180 bottom
C376  10uF  [CAP0603_1]  135.32 117.67 0 bottom
C377  10uF  [CAP0603_1]  131.13 117.67 180 bottom
C378  1uF  [CAP0402_0-75]  31.61 117.14 180 bottom
C379  0.1uF  [CAP0201_0-5]  109.83 116.92 0 bottom
C380  0.01uF  [CAP0201_0-5]  182.44 116.9 0 bottom
C381  10uF  [CAP0603_1]  29.59 116.44 270 bottom
C382  1uF  [CAP0402_0-75]  135.19 116.2 0 bottom
C383  1uF  [CAP0402_0-75]  131.19 116.2 180 bottom
C384  10uF  [CAP0603_1]  158.94 116.01 180 bottom
C385  0.01uF  [CAP0201_0-5]  181.21 115.95 180 bottom
C386  1uF  [CAP0402_0-75]  157.04 115.76 90 bottom
C387  0.01uF  [CAP0201_0-5]  184.21 115.73 90 bottom
C388  1uF  [CAP0402_0-75]  31.61 115.64 180 bottom
C389  0.1uF  [CAP0201_0-5]  57.79 115.51 270 bottom
C390  1uF  [CAP0402_0-75]  135.19 115.06 0 bottom
C391  1uF  [CAP0402_0-75]  131.19 115.19 180 bottom
C392  1uF  [CAP0402_0-75]  43.37 114.74 0 bottom
C393  1uF  [CAP0402_0-75]  31.61 114.14 180 bottom
C394  1uF  [CAP0402_0-75]  43.37 113.28 0 bottom
C395  0.1uF  [CAP0201_0-5]  109.83 112.02 180 bottom
C396  0.1uF  [CAP0201_0-5]  82.89 110.63 90 bottom
C397  0.1uF  [CAP0201_0-5]  81.66 110.42 180 bottom
C398  0.01uF  [CAP0201_0-5]  180.93 110.39 180 bottom
C399  1uF  [CAP0402_0-75]  39.83 110.11 270 bottom
C400  1uF  [CAP0402_0-75]  37.33 110.11 270 bottom
C401  18pF  [CAP0402_0-75]  127.44 109.76 90 bottom
C402  0.01uF  [CAP0201_0-5]  182.41 108.4 0 bottom
C403  10uF  [CAP0603_1]  40.64 108.2 0 bottom
C404  10uF  [CAP0603_1]  36.45 108.2 180 bottom
C405  1000pF  [CAP1206]  18.8 108.21 270 bottom
C406  1uF  [CAP0402_0-75]  53.15 107.75 90 bottom
C407  1uF  [CAP0402_0-75]  51.44 107.75 90 bottom
C408  1uF  [CAP0402_0-75]  165.99 107.63 90 bottom
C409  1uF  [CAP0402_0-75]  164.85 107.63 90 bottom
C410  10uF  [CAP0603_1]  167.45 107.57 90 bottom
C411  0.01uF  [CAP0201_0-5]  187.88 107.25 270 bottom
C412  18pF  [CAP0402_0-75]  127.38 106.84 270 bottom
C413  1uF  [CAP0402_0-75]  130.21 105.42 180 bottom
C414  0.1uF  [CAP0201_0-5]  147.96 104.58 270 bottom
C415  0.1uF  [CAP0201_0-5]  147.13 104.58 270 bottom
C416  0.01uF  [CAP0201_0-5]  144.78 104.58 90 bottom
C417  0.1uF  [CAP0201_0-5]  149.54 104.52 270 bottom
C418  0.1uF  [CAP0201_0-5]  148.78 104.52 90 bottom
C419  0.1uF  [CAP0201_0-5]  152.34 104.2 0 bottom
C420  0.1uF  [CAP0201_0-5]  153.99 104.2 0 bottom
C421  0.01uF  [CAP0201_0-5]  143.57 104.2 0 bottom
C422  0.1uF  [CAP0201_0-5]  141.92 104.2 0 bottom
C423  0.1uF  [CAP0201_0-5]  150.81 104.2 0 bottom
C424  1uF  [CAP0402_0-75]  46.34 103.98 180 bottom
C425  0.1uF  [CAP0201_0-5]  146.37 103.82 270 bottom
C426  0.1uF  [CAP0201_0-5]  145.54 103.82 90 bottom
C427  10uF  [CAP0603_1]  167.45 103.76 270 bottom
C428  1uF  [CAP0402_0-75]  165.99 103.57 270 bottom
C429  1uF  [CAP0402_0-75]  164.85 103.57 270 bottom
C430  0.1uF  [CAP0201_0-5]  137.48 103.39 0 bottom
C431  0.1uF  [CAP0201_0-5]  153.16 103.38 0 bottom
C432  0.1uF  [CAP0201_0-5]  149.99 103.38 0 bottom
C433  0.1uF  [CAP0201_0-5]  143.57 103.38 180 bottom
C434  0.01uF  [CAP0201_0-5]  182.44 103.19 0 bottom
C435  0.1uF  [CAP0201_0-5]  147.83 103.06 270 bottom
C436  0.1uF  [CAP0201_0-5]  154.37 103 270 bottom
C437  0.1uF  [CAP0201_0-5]  151.96 103 90 bottom
C438  0.1uF  [CAP0201_0-5]  151.13 103 270 bottom
C439  0.1uF  [CAP0201_0-5]  148.72 103 90 bottom
C440  0.1uF  [CAP0201_0-5]  114.81 103 180 top
C441  0.1uF  [CAP0201_0-5]  153.16 102.62 180 bottom
C442  0.1uF  [CAP0201_0-5]  146.75 102.62 0 bottom
C443  0.1uF  [CAP0201_0-5]  145.16 102.62 0 bottom
C444  0.1uF  [CAP0201_0-5]  149.99 102.62 180 bottom
C445  0.1uF  [CAP0201_0-5]  143.57 102.55 0 bottom
C446  1uF  [CAP0402_0-75]  46.34 102.48 180 bottom
C447  0.01uF  [CAP0201_0-5]  181.22 102.37 180 bottom
C448  0.1uF  [CAP0201_0-5]  141.92 102.17 225 bottom
C449  0.01uF  [CAP0201_0-5]  184.21 101.94 90 bottom
C450  0.1uF  [CAP0201_0-5]  136.76 101.87 270 bottom
C451  0.1uF  [CAP0201_0-5]  152.34 101.79 180 bottom
C452  0.1uF  [CAP0201_0-5]  149.92 101.79 0 bottom
C453  1uF  [CAP0402_0-75]  58.1 101.59 0 bottom
C454  0.1uF  [CAP0201_0-5]  154.37 101.41 270 bottom
C455  0.1uF  [CAP0201_0-5]  153.54 101.41 90 bottom
C456  0.1uF  [CAP0201_0-5]  151.13 101.41 270 bottom
C457  0.1uF  [CAP0201_0-5]  148.81 101.41 90 bottom
C458  1uF  [CAP0402_0-75]  147.89 101.41 270 bottom
C459  0.1uF  [CAP0201_0-5]  144.78 101.41 90 bottom
C460  10uF  [CAP0603_1]  168.97 101.09 90 bottom
C461  10uF  [CAP0603_1]  167.45 101.09 90 bottom
C462  1uF  [CAP0402_0-75]  165.99 101.09 90 bottom
C463  1uF  [CAP0402_0-75]  164.85 101.09 90 bottom
C464  0.1uF  [CAP0201_0-5]  130.46 101.05 180 bottom
C465  0.1uF  [CAP0201_0-5]  149.92 101.03 180 bottom
C466  1uF  [CAP0402_0-75]  46.34 100.99 180 bottom
C467  0.1uF  [CAP0201_0-5]  152.34 100.97 0 bottom
C468  0.1uF  [CAP0201_0-5]  146.69 100.97 0 bottom
C469  0.1uF  [CAP0201_0-5]  143.57 100.97 0 bottom
C470  0.1uF  [CAP0201_0-5]  141.99 100.97 0 bottom
C471  10uF  [CAP0603_1]  60.41 100.65 270 bottom
C472  0.1uF  [CAP0201_0-5]  145.54 100.58 90 bottom
C473  0.1uF  [CAP0201_0-5]  153.1 100.2 0 bottom
C474  0.01uF  [CAP0201_0-5]  151.51 100.2 0 bottom
C475  0.1uF  [CAP0201_0-5]  144.4 100.2 0 bottom
C476  0.1uF  [CAP0201_0-5]  142.81 100.2 0 bottom
C477  1uF  [CAP0402_0-75]  58.1 100.13 0 bottom
C478  0.1uF  [CAP0201_0-5]  141.54 99.82 90 bottom
C479  0.1uF  [CAP0201_0-5]  146.37 99.69 90 bottom
C480  0.1uF  [CAP0201_0-5]  130.67 99.69 90 bottom
C481  1uF  [CAP0402_0-75]  129.67 99.63 270 bottom
C482  1uF  [CAP0402_0-75]  147.89 99.57 270 bottom
C483  0.1uF  [CAP0201_0-5]  153.99 99.38 0 bottom
C484  0.1uF  [CAP0201_0-5]  152.34 99.38 0 bottom
C485  0.1uF  [CAP0201_0-5]  150.75 99.38 0 bottom
C486  0.1uF  [CAP0201_0-5]  149.1 99.38 0 bottom
C487  0.1uF  [CAP0201_0-5]  144.34 99.38 180 bottom
C488  0.1uF  [CAP0201_0-5]  142.81 99.38 180 bottom
C489  1000pF  [CAP1206]  10.09 103.26 90 bottom
C490  0.1uF  [CAP0201_0-5]  145.54 99 90 bottom
C491  0.1uF  [CAP0201_0-5]  146.75 98.74 180 bottom
C492  10uF  [CAP0603_1]  168.97 98.62 270 bottom
C493  0.1uF  [CAP0201_0-5]  154.75 98.62 0 bottom
C494  0.1uF  [CAP0201_0-5]  143.64 98.62 180 bottom
C495  0.1uF  [CAP0201_0-5]  141.99 98.62 180 bottom
C496  10uF  [CAP0603_1]  167.45 98.55 270 bottom
C497  1uF  [CAP0402_0-75]  166.12 98.55 270 bottom
C498  1uF  [CAP0402_0-75]  164.97 98.55 270 bottom
C499  10uF  [CAP0603_1]  44.45 98.38 180 bottom
C500  0.1uF  [CAP0201_0-5]  147.83 97.92 0 bottom
C501  0.01uF  [CAP0201_0-5]  138.75 97.92 180 bottom
C502  1uF  [CAP0402_0-75]  151.19 97.85 0 bottom
C503  1uF  [CAP0402_0-75]  149.42 97.85 180 bottom
C504  0.01uF  [CAP0201_0-5]  157.73 97.79 0 bottom
C505  0.01uF  [CAP0201_0-5]  155.89 97.79 180 bottom
C506  0.1uF  [CAP0201_0-5]  154.62 97.79 0 bottom
C507  0.1uF  [CAP0201_0-5]  153.54 97.79 90 bottom
C508  0.1uF  [CAP0201_0-5]  152.59 97.79 90 bottom
C509  1uF  [CAP0402_0-75]  146.18 97.79 0 bottom
C510  1uF  [CAP0402_0-75]  144.34 97.73 0 bottom
C511  1uF  [CAP0402_0-75]  142.56 97.73 180 bottom
C512  1uF  [CAP0402_0-75]  54.57 96.96 270 bottom
C513  1uF  [CAP0402_0-75]  52.07 96.96 270 bottom
C514  0.01uF  [CAP0201_0-5]  152.78 96.58 90 bottom
C515  0.1uF  [CAP0201_0-5]  150.37 96.58 90 bottom
C516  1uF  [CAP0402_0-75]  147.89 96.58 90 bottom
C517  0.1uF  [CAP0201_0-5]  146.37 96.58 270 bottom
C518  0.1uF  [CAP0201_0-5]  145.54 96.58 90 bottom
C519  0.1uF  [CAP0201_0-5]  144.34 96.58 135 bottom
C520  0.1uF  [CAP0201_0-5]  143.13 96.52 270 bottom
C521  0.1uF  [CAP0201_0-5]  141.54 96.52 270 bottom
C522  0.1uF  [CAP0201_0-5]  170.57 96.41 0 bottom
C523  0.1uF  [CAP0201_0-5]  153.99 96.2 0 bottom
C524  0.1uF  [CAP0201_0-5]  151.96 95.76 270 bottom
C525  0.1uF  [CAP0201_0-5]  151.13 95.76 90 bottom
C526  0.1uF  [CAP0201_0-5]  149.54 95.76 90 bottom
C527  0.1uF  [CAP0201_0-5]  142.75 95.38 180 bottom
C528  0.01uF  [CAP0201_0-5]  180.88 95.37 180 bottom
C529  10uF  [CAP0603_1]  51.3 95.06 180 bottom
C530  0.1uF  [CAP0201_0-5]  150.37 95 90 bottom
C531  0.1uF  [CAP0201_0-5]  146.37 95 270 bottom
C532  0.1uF  [CAP0201_0-5]  145.61 95 90 bottom
C533  0.1uF  [CAP0201_0-5]  143.95 95 90 bottom
C534  1uF  [CAP0402_0-75]  147.89 94.81 90 bottom
C535  0.1uF  [CAP0201_0-5]  152.34 94.61 0 bottom
C536  0.1uF  [CAP0201_0-5]  142.75 94.61 0 bottom
C537  0.1uF  [CAP0201_0-5]  141.22 94.61 0 bottom
C538  0.01uF  [CAP0201_0-5]  182.41 94.6 0 bottom
C539  0.1uF  [CAP0201_0-5]  144.78 94.17 90 bottom
C540  0.1uF  [CAP0201_0-5]  151.54 94.16 315 bottom
C541  2.2uF  [CAP0402_0-75]  168.53 94.02 90 bottom
C542  0.01uF  [CAP0201_0-5]  141.99 93.85 0 bottom
C543  0.1uF  [CAP0201_0-5]  148.84 94.23 90 bottom
C544  0.01uF  [CAP0201_0-5]  187.88 93.54 270 bottom
C545  0.1uF  [CAP0201_0-5]  155.19 93.41 90 bottom
C546  0.1uF  [CAP0201_0-5]  149.96 93.79 180 bottom
C547  0.1uF  [CAP0201_0-5]  146.75 93.41 45 bottom
C548  0.1uF  [CAP0201_0-5]  143.51 93.41 45 bottom
C549  0.1uF  [CAP0201_0-5]  145.54 93.34 90 bottom
C550  1uF  [CAP0402_0-75]  147.89 93.03 270 bottom
C551  0.1uF  [CAP0201_0-5]  141.99 93.03 180 bottom
C552  0.01uF  [CAP0201_0-5]  153.16 92.96 0 bottom
C553  0.1uF  [CAP0201_0-5]  144.78 92.65 90 bottom
C554  0.1uF  [CAP0201_0-5]  149.54 92.58 270 bottom
C555  0.1uF  [CAP0201_0-5]  144.08 92.58 270 bottom
C556  0.01uF  [CAP0201_0-5]  150.37 92.58 90 bottom
C557  0.1uF  [CAP0201_0-5]  154.37 92.52 270 bottom
C558  0.1uF  [CAP0201_0-5]  145.99 92.2 180 bottom
C559  0.1uF  [CAP0201_0-5]  155.19 91.82 270 bottom
C560  0.1uF  [CAP0201_0-5]  142.75 91.82 315 bottom
C561  0.1uF  [CAP0201_0-5]  153.56 91.78 270 bottom
C562  0.1uF  [CAP0201_0-5]  141.54 91.76 270 bottom
C563  0.1uF  [CAP0201_0-5]  146.94 91.63 90 bottom
C564  1uF  [CAP0402_0-75]  164.83 92.08 0 bottom
C565  0.1uF  [CAP0201_0-5]  147.89 91.44 90 bottom
C566  0.1uF  [CAP0201_0-5]  151.56 91.38 0 bottom
C567  0.1uF  [CAP0201_0-5]  149.16 91.38 180 bottom
C568  0.1uF  [CAP0201_0-5]  145.92 91.38 0 bottom
C569  0.1uF  [CAP0201_0-5]  144.27 91.38 0 bottom
C570  1uF  [CAP0402_0-75]  170.12 91.31 180 bottom
C571  0.1uF  [CAP0201_0-5]  150.77 91 315 bottom
C572  0.1uF  [CAP0201_0-5]  152.77 90.97 270 bottom
C573  0.1uF  [CAP0201_0-5]  144.27 90.61 180 bottom
C574  0.1uF  [CAP0201_0-5]  141.99 90.61 0 bottom
C575  0.1uF  [CAP0201_0-5]  153.96 90.57 0 bottom
C576  1uF  [CAP0402_0-75]  170.12 90.11 180 bottom
C577  0.1uF  [CAP0201_0-5]  54.57 90.05 90 bottom
C578  0.1uF  [CAP0201_0-5]  52.07 90.05 90 bottom
C579  0.01uF  [CAP0201_0-5]  182.44 89.47 0 bottom
C580  0.1uF  [CAP0201_0-5]  164.4 89.45 270 bottom
C581  0.1uF  [CAP0201_0-5]  91.38 88.84 90 bottom
C582  0.1uF  [CAP0201_0-5]  64.96 88.63 180 bottom
C583  0.01uF  [CAP0201_0-5]  181.22 88.58 180 bottom
C584  18pF  [CAP0402_0-75]  168.53 88.44 90 bottom
C585  0.01uF  [CAP0201_0-5]  184.13 88.23 90 bottom
C586  0.1uF  [CAP0201_0-5]  58.1 86.88 0 bottom
C587  18pF  [CAP0402_0-75]  168.53 86.53 270 bottom
C588  0.1uF  [CAP0201_0-5]  46.34 86.02 180 bottom
C589  0.1uF  [CAP0201_0-5]  58.1 85.41 0 bottom
C590  0.1uF  [CAP0201_0-5]  46.34 84.52 180 bottom
C591  0.1uF  [CAP0201_0-5]  91.25 83.12 270 bottom
C592  0.1uF  [CAP0201_0-5]  46.34 83.02 180 bottom
C593  0.01uF  [CAP0201_0-5]  181 82.92 180 bottom
C594  0.01uF  [CAP0201_0-5]  182.41 80.87 0 bottom
C595  0.1uF  [CAP0201_0-5]  156.34 80.21 270 bottom
C596  0.01uF  [CAP0201_0-5]  150.5 79.88 180 bottom
C597  0.01uF  [CAP0201_0-5]  187.81 79.82 270 bottom
C598  0.1uF  [CAP0201_0-5]  53.12 79.26 270 bottom
C599  0.1uF  [CAP0201_0-5]  51.41 79.26 270 bottom
C600  18pF  [CAP0402_0-75]  80.77 78.49 90 bottom
C601  0.01uF  [CAP0201_0-5]  31.24 76.01 270 bottom
C602  18pF  [CAP0402_0-75]  80.77 76.58 270 bottom
C603  0.1uF  [CAP0201_0-5]  90.97 75.18 180 bottom
C604  0.1uF  [CAP0201_0-5]  179.47 69.41 90 bottom
C605  22uF_6.3V  [CAP0603]  36.83 66.17 90 bottom
C606  10uF  [CAP1206_2]  32.83 65.91 0 bottom
C607  0.1uF  [CAP0201_0-5]  185.42 62.62 270 bottom
C608  0.1uF  [CAP0201_0-5]  191.73 62.41 0 bottom
C609  0.1uF  [CAP0201_0-5]  46.23 62.31 0 top
C610  0.1uF  [CAP0201_0-5]  43.46 61.34 180 bottom
C611  0.1uF  [CAP0201_0-5]  42.13 61.34 0 bottom
C612  1uF  [CAP0402_0-75]  46.17 61.29 0 top
C613  0.1uF  [CAP0201_0-5]  144.15 59.36 270 bottom
C614  0.1uF  [CAP0201_0-5]  142.65 59.36 270 bottom
C615  0.1uF  [CAP0201_0-5]  57.26 55.71 90 bottom
C616  0.1uF  [CAP0201_0-5]  55.76 55.71 90 bottom
C617  2.2uF  [CAP0402_0-75]  161.73 54.67 180 bottom
C618  1uF  [CAP0402_0-75]  159.7 54.67 0 bottom
C619  0.1uF  [CAP0201_0-5]  184.53 53.8 90 bottom
C620  0.1uF  [CAP0201_0-5]  159.7 53.72 0 bottom
C621  0.01uF  [CAP0201_0-5]  40.58 53.44 90 bottom
C622  0.1uF  [CAP0201_0-5]  161.3 52.49 270 bottom
C623  2.2uF  [CAP0402_0-75]  163.84 51.78 90 bottom
C624  0.01uF  [CAP0201_0-5]  147.13 49.8 180 bottom
C625  0.1uF  [CAP0201_0-5]  160.18 47.6 0 bottom
C626  0.1uF  [CAP0201_0-5]  54.81 47.08 270 bottom
C627  0.1uF  [CAP0201_0-5]  184.53 47 270 bottom
C628  1uF  [CAP0402_0-75]  168.37 45.9 0 bottom
C629  0.1uF  [CAP0201_0-5]  54.81 45.52 90 bottom
C630  0.1uF  [CAP0201_0-5]  168.47 44.89 0 bottom
C631  0.1uF  [CAP0201_0-5]  129.41 44.56 0 bottom
C632  0.1uF  [CAP0201_0-5]  129.41 42.66 0 bottom
C633  0.1uF  [CAP0201_0-5]  48.94 39.25 180 bottom
C634  0.1uF  [CAP0201_0-5]  54.6 38.99 90 bottom
C635  0.1uF  [CAP0201_0-5]  144.65 38.53 0 bottom
C636  0.1uF  [CAP0201_0-5]  144.65 36.63 0 bottom
C637  0.1uF  [CAP0201_0-5]  111.17 36.24 0 bottom
C638  0.1uF  [CAP0201_0-5]  168.55 34.94 0 bottom
C639  0.1uF  [CAP0201_0-5]  152.51 34.88 180 bottom
C640  1uF  [CAP0402_0-75]  168.75 33.92 0 bottom
C641  1uF  [CAP0402_0-75]  152.43 33.86 180 bottom
C642  0.01uF  [CAP0201_0-5]  53.89 33.53 0 bottom
C643  1uF  [CAP0402_0-75]  199.07 31.29 90 bottom
C644  0.1uF  [CAP0201_0-5]  200.09 31.23 90 bottom
C645  0.1uF  [CAP0201_0-5]  63.69 29.78 0 bottom
C646  1uF  [CAP0402_0-75]  65.09 29.4 90 bottom
C647  0.1uF  [CAP0201_0-5]  63.69 28.92 0 bottom
C648  0.1uF  [CAP0201_0-5]  199.74 28.05 270 bottom
C649  1uF  [CAP0402_0-75]  198.72 28.03 270 bottom
C650  0.1uF  [CAP0201_0-5]  63.82 24.92 0 bottom
C651  2.2uF  [CAP0402_0-75]  64.07 22.74 0 bottom
C652  12pF  [CAP0402]  65.6 21.95 270 bottom
C653  1uF  [CAP0402_0-75]  64.07 21.72 0 bottom
C654  0.01uF  [CAP0201_0-5]  45.09 21.52 90 bottom
C655  0.1uF  [CAP0201_0-5]  42.23 21.52 90 bottom
C656  0.1uF  [CAP0201_0-5]  135.68 21.29 270 bottom
C657  0.01uF  [CAP0201_0-5]  44.83 20.52 180 bottom
C658  0.1uF  [CAP0201_0-5]  80.27 20.32 90 bottom
C659  12pF  [CAP0402]  65.6 20.04 90 bottom
C660  1uF  [CAP0402_0-75]  42.1 19.72 270 bottom
C661  0.1uF  [CAP0201_0-5]  207.67 159.46 0 bottom
C662  0.1uF  [CAP0201_0-5]  207.66 160.28 0 bottom
C663  0.1uF  [CAP0201_0-5]  145.99 18.16 90 bottom
C664  0.1uF  [CAP0201_0-5]  139.39 17.83 180 bottom
C665  0.1uF  [CAP0201_0-5]  63.84 17.46 0 bottom
C666  10uF  [CAP0603_1]  152.4 16 0 bottom
C667  0.1uF  [CAP0201_0-5]  53.49 15.19 0 bottom
C668  0.01uF  [CAP0201_0-5]  58.89 14.8 270 bottom
C669  0.01uF  [CAP0201_0-5]  50.49 14.8 270 bottom
C670  1uF  [CAP0402_0-75]  154.05 14.1 180 bottom
C671  0.1uF  [CAP0201_0-5]  132.54 13.17 0 bottom
C672  0.1uF  [CAP0201_0-5]  74.42 11.44 270 bottom
C673  0.1uF  [CAP0201_0-5]  139.06 10.11 0 bottom
C674  0.1uF  [CAP0201_0-5]  139.06 9.2 0 bottom
C675  1uF  [CAP0402_0-75]  153.29 7.68 0 bottom
C676  10uF  [CAP0603_1]  153.29 6.22 0 bottom
C677  0.1uF  [CAP0201_0-5]  167.39 4.46 90 bottom
C679  4.7uF  [CAP0402_0-75]  97.41 136.1 270 bottom
C680  2.2uF  [CAP0805_1]  83.19 138.94 90 bottom
C681  2.2uF  [CAP0805_1]  83.31 134.87 270 bottom
C682  0.1uF  [CAP0201_0-5]  187.41 169.8 270 bottom
C683  33pF  [CAP0201_0-5]  86.33 160.41 0 bottom
C684  33pF  [CAP0201_0-5]  86.23 115.82 180 bottom
C685  0.01uF  [CAP0201_0-5]  161.16 151.28 0 top
C686  0.01uF  [CAP0201_0-5]  163.77 139.13 0 top
C687  0.01uF  [CAP0201_0-5]  101.73 77.22 180 bottom
C688  0.01uF  [CAP0201_0-5]  101.85 75.31 180 top
C689  0.01uF  [CAP0201_0-5]  101.85 73.15 180 bottom
C690  0.01uF  [CAP0201_0-5]  100.73 80.52 180 top
C691  4.7uF  [CAP0402_0-75]  143.87 145.92 90 bottom
C692  22uF  [CAP1206_2]  175.13 48.51 180 top
C693  0.1uF  [CAP0201_0-5]  180.59 63.63 180 bottom
C695  4.7uF  [CAP0402_0-75]  179.71 54.74 180 bottom
C696  1uF  [CAP0402_0-75]  180.47 64.64 180 bottom
D1  S1G-13-F  [DIO_SMA]  18.73 165.16 270 top
D2  SMCJ64CA  [DIO_SMC]  69.62 162.24 0 top
D3  SSB44-E3/52T  [DIO_SMB_2-5]  93.6 154.85 270 top
D4  BZX84C6V8LT1G  [SOT23-123_1-2]  20.11 155.53 180 top
D5  SSB44-E3/52T  [DIO_SMB_2-5]  88.57 154.85 270 top
D6  SK1545-TP  [DO-214AB_5-6]  59.44 149.86 0 top
D7  TPD1E10B06DPY  [DIO_DFN0402]  14.2 138.65 0 top
D8  SSB44-E3/52T  [DIO_SMB_2-5]  89.03 134.49 90 top
D9  SSB44-E3/52T  [DIO_SMB_2-5]  93.73 134.49 90 top
D10  TPD1E10B06DPY  [DIO_DFN0402]  140.53 32.23 270 top
D11  TPD1E10B06DPY  [DIO_DFN0402]  109.59 33.02 90 top
D12  TPD1E10B06DPY  [DIO_DFN0402]  156.07 32.3 270 top
D13  TPD1E10B06DPY  [DIO_DFN0402]  125.03 33.07 90 top
D14  BZT52C13S  [DIO_SOD323]  22.61 163.58 180 bottom
D15  XBS104S13R  [DIO_SOD323_1]  93.85 139.95 270 bottom
D16  BZX84C6V8LT1G  [SOT23-123_1-2]  146.33 147.14 270 bottom
D17  XBS104S13R  [DIO_SOD323_1]  93.85 135 90 bottom
F1  10A  [FUSE_397_410X110_SMD_2-9]  57.28 159.51 0 top
FL1  120E  [EMIFIL_BLM15A_0402_0-6]  194.82 147.26 180 top
FL2  4.7uF  [EMIFIL_NFM21P_0805_1]  18.22 144.54 90 top
FL3  120E  [EMIFIL_BLM15A_0402_0-6]  76.71 95.38 90 top
FL4  120E  [EMIFIL_BLM15A_0402_0-6]  70.1 91.57 90 top
FL5  120E  [EMIFIL_BLM15A_0402_0-6]  88.87 81.22 0 top
FL6  120E  [EMIFIL_BLM15A_0402_0-6]  97.42 1.57 180 bottom
FL7  120E  [EMIFIL_BLM15A_0402_0-6]  24.51 173.72 180 bottom
FL8  90E  [IND4_ACM2012_90X50_SMD_1-3]  18.16 158.88 180 bottom
FL9  220E  [EMIFIL_BLM15A_0402]  16.64 139.57 180 bottom
FL10  220E  [EMIFIL_BLM15A_0402]  16.64 138.43 180 bottom
FL11  120E  [EMIFIL_BLM15A_0402_0-6]  29.94 123.9 180 bottom
FL12  120E  [EMIFIL_BLM15A_0402_0-6]  32.69 97.92 270 bottom
FL13  240E  [EMIFIL_BLM03B_0201]  153.97 94.99 135 bottom
FL14  120E  [EMIFIL_BLM15A_0402_0-6]  32.69 86.08 90 bottom
FL15  120E  [EMIFIL_BLM15A_0402_0-6]  199.79 33.35 0 bottom
FL16  120E  [EMIFIL_BLM18R_0603_1]  130.09 104.09 0 bottom
FL17  26E  [EMIFIL_BLM18K_0603]  147 115.64 270 bottom
FL18  120E  [EMIFIL_BLM18R_0603_1]  130.07 102.45 0 bottom
FL19  26E  [EMIFIL_BLM18K_0603]  166.42 89.78 180 bottom
FL20  26E  [EMIFIL_BLM18K_0603]  166.85 92.9 270 bottom
FL21  120E  [EMIFIL_BLM18R_0603_1]  154.89 80.9 90 top
FL22  120E  [EMIFIL_BLM18R_0603_1]  130.14 92.23 0 bottom
FL23  120E  [EMIFIL_BLM18R_0603_1]  154.05 115.91 270 bottom
FL24  120E  [EMIFIL_BLM18R_0603_1]  130.18 113.88 0 bottom
FL25  120E  [EMIFIL_BLM18R_0603_1]  126.39 114.77 270 bottom
FL26  120E  [EMIFIL_BLM18R_0603_1]  152.53 115.85 270 bottom
FL27  120E  [EMIFIL_BLM18R_0603_1]  130.14 95.75 0 bottom
FL28  120E  [EMIFIL_BLM18R_0603_1]  155.12 80.57 90 bottom
FL29  120E  [EMIFIL_BLM18R_0603_1]  130.16 112.39 0 bottom
FL30  120E  [EMIFIL_BLM18R_0603_1]  130.14 97.27 0 bottom
FL31  120E  [EMIFIL_BLM18R_0603_1]  151 115.85 270 bottom
FL32  120E  [EMIFIL_BLM18R_0603_1]  155.58 115.91 270 bottom
FL33  120E  [EMIFIL_BLM18R_0603_1]  152.36 80.57 90 bottom
FL34  120E  [EMIFIL_BLM18R_0603_1]  130.14 94.23 0 bottom
FL35  120E  [EMIFIL_BLM18R_0603_1]  126.73 112.39 180 bottom
FL36  120E  [EMIFIL_BLM18R_0603_1]  170.82 95.19 180 bottom
FL37  0.0E_  [RES0603]  175.77 51.73 0 top
FL38  120E  [EMIFIL_BLM15A_0402_0-6]  177.67 47.5 90 top
J1  CON_PWRJACK3_RAPC722  [CON_PWRJACK3_RAPC722_P_R_T]  54.85 164.45 180 top
J2  CON_POWERJACK4_PD-40S  [CON_POWERJACK4_PD-40S_S_R_T_15]  37.33 163.37 0 top
J3  CON_MUSB-AB_5_F  [CON_USBAB5_475900001_S_R_S_3-1]  9.07 159.77 270 top
J4  HDR_2X3  [HDR_2X3_TSW-103-07-D_S_T_8-4]  8.51 152.97 270 top
J5  CON_BTOB_2X30_171446_M  [CON_BTOB2X30_171446_P_S_S_5-5]  146.14 146.96 180 top
J6  HDR_2X5  [HDR_2X5_TFC-105-01-D-A_S_T_5-6]  125.79 147.47 180 top
J8  HDR_1X3  [HDR_3X1_100_S_T]  127.57 137.91 180 bottom
J9  HDR_1X3  [HDR_1X3_440054-3_S_T_6-4]  106.01 123.92 0 top
J10  HDR_2X10  [HDR_2X10_TSW_100_S_T]  152.4 130.26 180 top
J11  HDR_1X6  [HDR_6X1_100_S_T]  116.33 116.01 270 top
J12  CON_RJ45-14_LPJG16314A4NL  [CON_RJ45-14_LPJG16314A4NL_S_R_T_13-6]  26.92 125.17 270 top
J13  CON_10X2  [CON_10X2_FTR-110-51-S-D_P_S_S]  102.23 93.22 270 top
J14  CON_RJ45-28_LPJG17512AONL  [CON_RJ45-28_LPJG17512_S_R_T_25-3]  22.53 95.31 270 top
J15  HDR_2X1  [HDR_2X1_100_S_T_10-8]  187.96 69.14 270 top
J16  CON_PMC_30X2_F  [CON_PMC30X2_QSH-030-01-L_S_S_S]  51.18 67.31 180 top
J17  CON_SDCARD9_1939870-1  [CON_SD9_1939870-1_S_R_S_2-9]  194.88 49.66 90 top
J18  CON_PMC_2X60_F  [CON_PMC60X2_HQCD-060_S_S_S_3-3]  80.26 46.61 90 top
J19  HDR_1X7  [HDR_1X7_22284070_S_T_8-4]  170.94 25.27 180 top
J20  HDR_1X5  [HDR_5X1_100_S_T_8-4]  185.38 30.99 180 top
J21  HDR_1X5  [HDR_5X1_100_S_T_11-2]  108.03 24.9 90 top
J22  CON_PMC_20X2_F  [CON_PMC20X2_QSH-D-DP_S_S_S]  161.04 11.62 0 top
J23  CON_MUSB-B_5_F  [CON_MUSBB5_1051640001_S_R_S_2-5]  103.44 1.97 0 top
J24  HDR_2X1  [HDR_2X1_100_S_T_10-8]  183.94 165.47 180 bottom
J25  HDR_2X1  [HDR_2X1_100_S_T_10-8]  159.19 166.35 90 bottom
J26  HDR_2X1  [HDR_2X1_100_S_T_10-8]  148.59 161.8 180 bottom
J27  HDR_2X1  [HDR_2X1_100_S_T_10-8]  133.2 161.8 0 bottom
J28  HDR_2X1  [HDR_2X1_100_S_T_10-8]  174.1 157.1 180 bottom
J29  HDR_2X1  [HDR_2X1_100_S_T_10-8]  166.18 156.84 0 bottom
J30  HDR_1X6  [HDR_1X6_22052061_R_T_6-3]  87.88 169.8 180 top
J31  HDR_2X1  [HDR_2X1_100_S_T_10-8]  113.44 111.51 180 bottom
J32  CON_PMC_30X2_F  [CON_PMC30X2_QSH-030-01-L_S_S_S]  102.23 93.22 270 bottom
J33  HDR_1X3  [HDR_3X1_100_S_T]  42.89 90.17 270 top
J34  CON_10X2  [CON_10X2_FTR-110-51-S-D_P_S_S]  43.62 48.11 0 bottom
J35  CON_PMC_2X60_F  [CON_PMC60X2_HQCD-060_S_S_S_3-3]  170.79 39.88 0 bottom
J36  CON_PMC_30X2_F  [CON_PMC30X2_QSH-030-01-L_S_S_S]  160.79 39.88 0 bottom
J37  HDR_1X3  [HDR_3X1_100_S_T]  131.95 24.51 180 top
J38  CON_FLEX_1X40_20720-040  [CON_FLEX1X40_20720-040_S_R_S_2]  203.99 20.45 270 bottom
J39  CON_FLEX_1X36_52559-3652  [CON_FLEX1X36_52559-36_S_S_S_5-3]  161.29 10.86 0 bottom
J40  TC2050-IDC-NL  [CON_2X5_TC2050-IDC-430-NL_T]  57.98 6.16 0 bottom
J41  CON_FLEX_40X1_FH12A-40S-0.5SH  [CON_FLEX40X1_FH12A_S_R_S]  129.1 3.56 180 bottom
J42  CON_MUSB-B_5_F  [CON_MUSBB5_1051640001_S_R_S_2-5]  8.95 140.97 270 top
J43  HDR_1X3  [HDR_3X1_100_S_T]  126.49 24.51 0 top
J44  HDR_1X3  [HDR_3X1_100_S_T]  171.45 33.15 180 top
J45  HDR_1X3  [HDR_3X1_100_S_T]  171.45 29.08 180 top
L1  10uH  [IND_ETQP5MYFM_310X290_SMD_5-4]  98.17 145.16 90 top
L2  1uH  [IND_IHLP2020AB_210X210_SMD_1-2]  38.29 76.53 270 top
L3  0.47uH  [IND_XEL4030_170X170_SMD_1-6]  179.71 172.23 270 bottom
L4  0.47uH  [IND_XEL4030_170X170_SMD_1-6]  147.64 169.76 270 bottom
L5  0.47uH  [IND_XEL4030_170X170_SMD_1-6]  134.49 169.76 270 bottom
L6  1uH  [IND_IHLP2020AB_210X210_SMD_1-2]  166.78 162.13 0 bottom
L7  1uH  [IND_XFL4020_170X170_SMD_2-1]  116.33 160.97 0 bottom
L8  1.5uH  [IND_ETQP4MKVK_350X330_SMD_4]  94.23 148.37 270 bottom
L9  6.8uH  [IND_74439346068_260X270_SMD_6-1]  53.21 127.28 270 bottom
L10  1.5uH  [IND_ETQP4MKVK_350X330_SMD_4]  94.23 126.21 270 bottom
L11  0.47uH  [IND_XEL4030_170X170_SMD_1-6]  34.14 62.17 0 bottom
LD1  598-8110-107F  [LED_0805]  18.73 173.56 270 top
LD2  598-8170-107F  [LED_0805_0-7]  75.37 172.68 90 top
LD3  598-8170-107F  [LED_0805_0-7]  79.63 172.53 90 top
LD4  598-8170-107F  [LED_0805_0-7]  83.82 172.44 90 top
LD5  598-8170-107F  [LED_0805_0-7]  21.87 172.72 270 top
LD6  598-8110-107F  [LED_0805]  11.1 166.8 0 top
LD7  SML-P11MTT86  [LED_0402_0-3]  8.81 131.83 90 top
LD8  598-8170-107F  [LED_0805_0-7]  48.01 116.71 90 top
LD9  598-8170-107F  [LED_0805_0-7]  50.8 116.71 90 top
LD10  598-8170-107F  [LED_0805_0-7]  56.39 116.71 90 top
LD11  598-8170-107F  [LED_0805_0-7]  59.05 116.71 90 top
LD12  598-8170-107F  [LED_0805_0-7]  61.85 116.71 90 top
LD13  598-8170-107F  [LED_0805_0-7]  64.77 116.71 90 top
LD14  598-8170-107F  [LED_0805_0-7]  67.44 116.71 90 top
LD15  598-8170-107F  [LED_0805_0-7]  53.57 116.7 90 top
LD16  598-8110-107F  [LED_0805]  72.7 107.19 270 top
LD17  598-8170-107F  [LED_0805_0-7]  62.99 103.57 270 top
LD18  SML-LX15IGC-TR  [LED3_SML-LX15IGC_120X120_SMD_1]  17.08 79.5 180 top
LD19  LP L296-J2L2-25  [LED_0603_0-7]  98.23 12.19 0 top
LD20  LS Q976-NR-1  [LED_0603_0-8]  98.48 9.78 0 top
NOREF  -  [unnamed]  164.53 173.99 0 top
NOREF#2  -  [#2]  3.68 17.53 0 top
NOREF#3  -  [#2]  6.99 3.53 0 top
NOREF#4  -  [unnamed]  3.49 168.4 0 top
NOREF#5  -  [#2]  -519.3 -180.47 0 top
NOREF#6  -  [unnamed]  206.38 173.99 0 top
NOREF#7  -  [unnamed]  117.35 173.99 0 top
NOREF#8  -  [unnamed]  87.71 72.99 0 top
NOREF#9  -  [#2]  85.61 15.92 0 top
NOREF#10  -  [unnamed]  213.68 168.4 0 top
NOREF#11  -  [#2]  85.5 23.36 0 top
NOREF#12  -  [#2]  0 0 0 top
